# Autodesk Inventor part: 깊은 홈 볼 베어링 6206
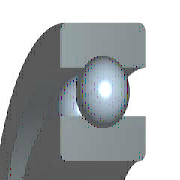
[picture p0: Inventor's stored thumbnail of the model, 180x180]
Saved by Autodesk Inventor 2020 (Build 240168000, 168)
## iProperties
Created: 2012-02
Part Number: 깊은 홈 볼 베어링 6206
Material: 강철, 연강
Description: 깊은 그루부 볼 베어링
Document SubType Name: Modeling
Standard: JIS B 1521
Designer: mdu-01
Standards Organization: JIS
Language: ko-KR
Size Designation: 6206 30x62x16
Categories: <MemberInstance><Categories><Category DisplayName="샤프트 부품" InternalName="7f7aeb1f-a693-4053-b835-cee3144e0d98" Mnemonic="SHFT"><Category DisplayName="베어링" Inter
Density: 7.85 g/cm^3
Appearance: 강철(1)
Mass: 196.318 g
Surface Area: 142.005 cm^2
Volume: 25.0086 cm^3
IsCustomPart: 1
Author: mdu-01
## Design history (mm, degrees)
sketch "스케치" dims "d0" = 8.32 (= -0.26 x WD + 0.26 x BD)
  geometry: L1 (3.84, 23)-(12.16, 23); L2 (8, 23)-(8, 18.84); L3 (8, 23)-(8, 27.16); L4 (4.909, 20.216)-(0, 20.216); L5 (0, 15)-(16, 15); L6 (4.909, 25.784)-(0, 25.784); L7 (0, 31)-(16, 31); L8 (16, 15)-(16, 20.216); L9 (11.091, 20.216)-(16, 20.216); L10 (11.091, 25.784)-(16, 25.784); L11 (16, 31)-(16, 25.784); L12 (-1.4, 0)-(8.4, 0) reference; L13 (0, -0.3)-(0, 5.3) reference
  constraints: 22 end point, 4 point on line, 2 collinear, 2 perpendicular, 2 symmetric about line, 1 midpoint, 1 parallel, 14 other
  dimensions: "d9" = 30 diameter of L5 L12 (= WD); "d11" = 62 diameter of L7 L12 (= BD); "d12" = 16 distance between parallel lines of L8 L13 (= KB); "d13" = 40.432 diameter of L9 L12 (= 0.326 x BD + 0.674 x WD)
revolve "본체" stored, may be unused: angle "d6" = 90 deg
revolve "볼" stored, may be unused: angle "d7" = 90 deg
pattern_circular "IDS_ARRAYBALL[SIMPL:T]" dims angle "d3" = 360 deg
body "Solid1"
fillet "모깎기1" dims "d1" = 1 (= KRS)
other parameters: "WD" = 30 [user parameter; used in 5 equation terms], "BD" = 62 [user parameter; used in 5 equation terms], "KB" = 16 [user parameter; used in 1 equation term], "KRS" = 1 [user parameter; used in 1 equation term], "d4" = 0, "d5" = 0, "d8" = 0, "d14" = 0, "d15" = 0, "BBA" = 0 [user parameter], "BC0" = 1.12e+07 [user parameter], "BC" = 1.95e+07 [user parameter], "BR" = 31 (= 0.5 x BD) [user parameter], "WR" = 15 (= 0.5 x WD) [user parameter]
